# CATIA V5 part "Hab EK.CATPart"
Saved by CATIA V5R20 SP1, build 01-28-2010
Part number: Hab EK
Bounding box of the stored display mesh (mm): x 0 to 20, y 201.569 to 350.616, z -437.308 to 13.658
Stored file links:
  D:\Catia\IAO\A rendre\Hab EK.CATPart
  D:\Catia\IAO\A rendre\Assemblage.CATProduct
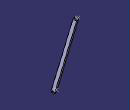
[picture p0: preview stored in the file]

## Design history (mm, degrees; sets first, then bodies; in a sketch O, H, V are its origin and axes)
Set1
  Point1: linked copy from another document
  Point2: linked copy from another document
Body1 (main body)
  Sketch1 on yz-plane, origin (0, 0, 0), H (0, 1, 0), V (0, 0, 1)
    construction line L1 (340.6677, 3.7093) -> (211.517, -427.3593)
    point P1 (340.6677, 3.7093)
    point P2 (211.517, -427.3593)
    line L2 (350.247, 0.8393) -> (221.0963, -430.2293)
    line L3 (201.9377, -424.4893) -> (331.0884, 6.5793)
    arc A1 centre (211.517, -427.3593) radius 10 from (221.0963, -430.2293) to (201.9377, -424.4893) cw
    arc A2 centre (340.6677, 3.7093) radius 10 from (331.0884, 6.5793) to (350.247, 0.8393) cw
    reference projected point E1 (211.517, -427.3593) from Point1
    reference projected point E2 (340.6677, 3.7093) from Point2
    circle A3 centre (340.6677, 3.7093) radius 5
    point P7 (340.6677, 3.7093)
    circle A4 centre (211.517, -427.3593) radius 5
    distance L1 L2 = 10
    radius A3 = 5
    radius A4 = 5
    tangency: A1 L2, A2 L2, A1 L3, A2 L3
    coincidence: P2 E1, P1 E2, P7 L1
  Pad1: profile Sketch1, direction (1, 0, 0), length 10, opposite side length -20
